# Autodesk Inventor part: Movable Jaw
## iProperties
Shininess: 77.0
Length Units: 11269
Angle Units: 11279
Time Units: 11290
Mass Units: 11283
Length Display Precision: 3
Angle Display Precision: 2
Created: 2002-02
Part Number: Movable Jaw
Document SubType Name: Modeling
Designer: ***
Density: 1 g/cm^3
Density: 0.0
Volumn: 0.0
Area: 0.0
PropertySet Name: Model Information
Control State: 0
Master: False
Checked Out: False
Author: ***
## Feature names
1. Extrusion1
2. Extrusion2
3. Hole1
4. Hole2
5. Mirror1
6. Hole3
